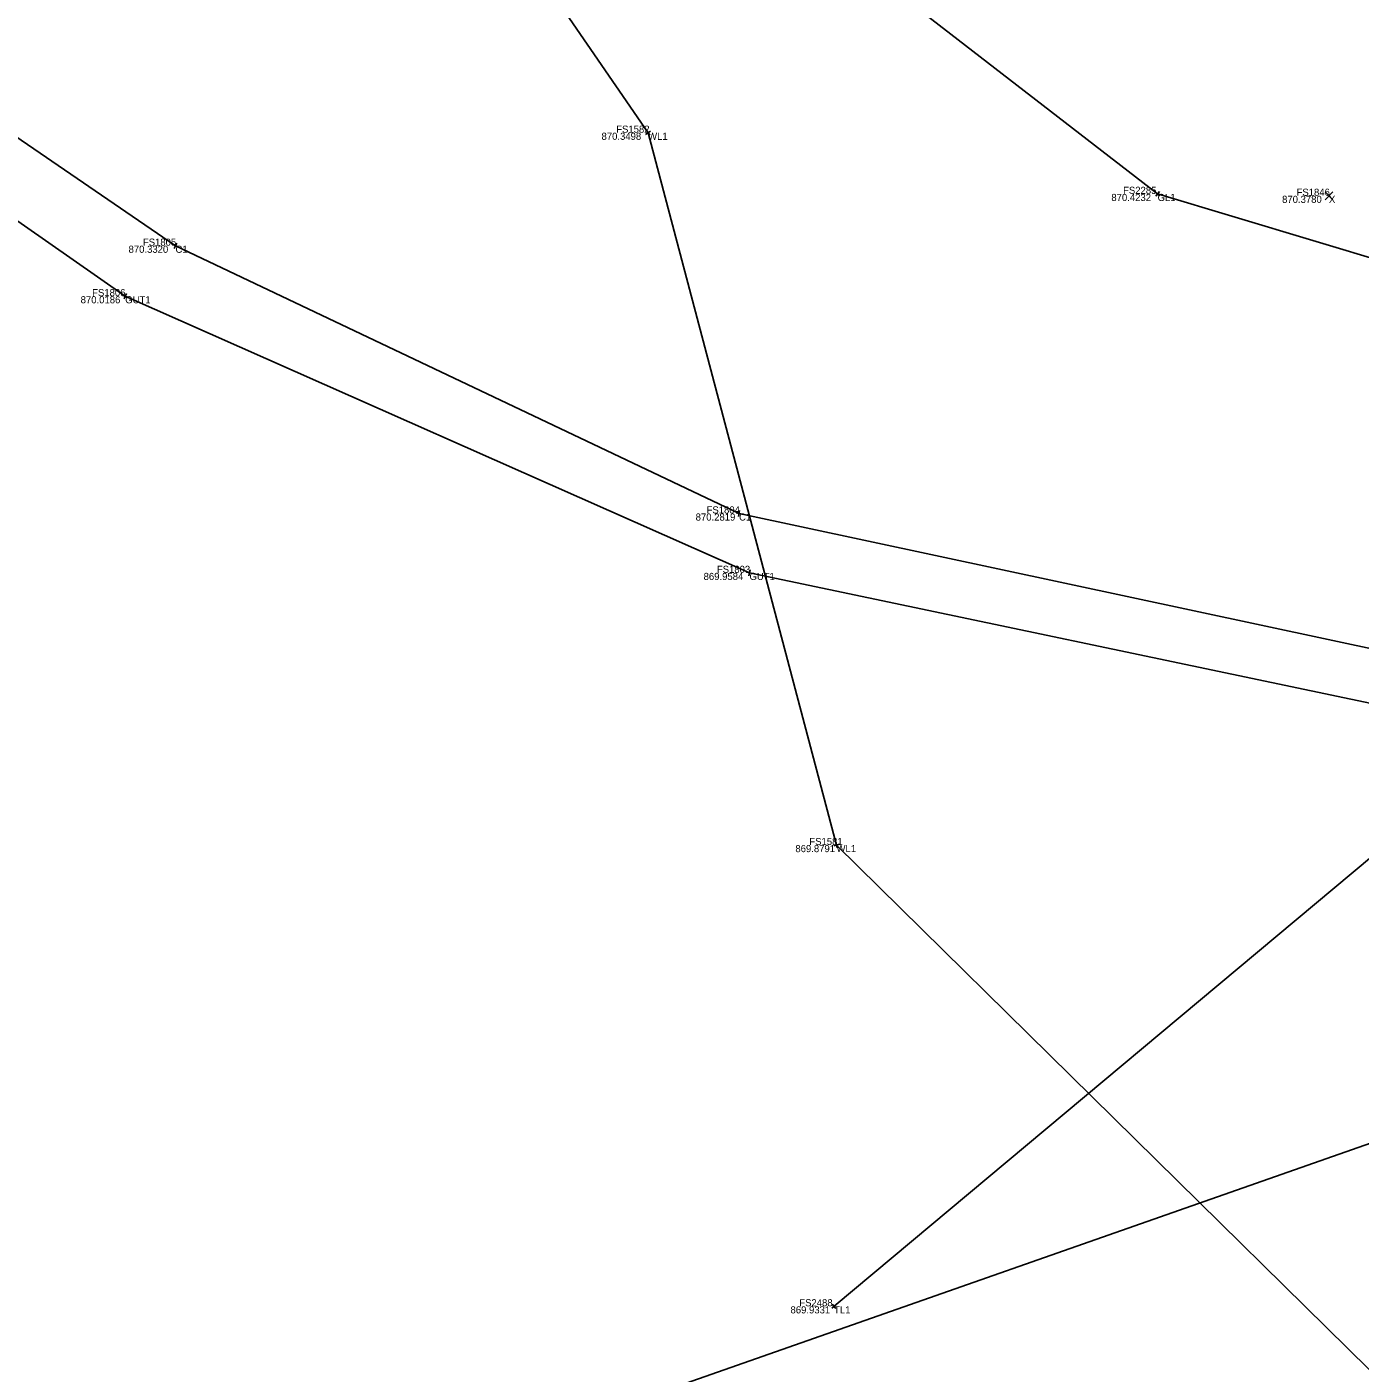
# Model space of a CAD drawing. Extents: x 1479425 to 1480294, y 379351 to 380102.
# Drawn here: x 1479647.93 to 1479659.17, y 379936.02 to 379947.37 of the extents above; entities that cross this region are included whole.
import ezdxf

# ---------------------------------------------------------------- set-up
doc = ezdxf.new("R2010")
doc.units = 0
for name, color, linetype in [('PV_X_Curb', 7, 'Continuous'), ('SV_X_Random_Point', 7, 'Continuous'), ('SV_X_Shot_Marker', 7, 'Continuous'), ('SV_X_Text_Comment', 7, 'Continuous'), ('SV_X_Text_Elevation', 7, 'Continuous'), ('SV_X_Text_Name', 7, 'Continuous'), ('UT_X_Gas', 7, 'Continuous'), ('UT_X_Sanitary_Line', 7, 'Continuous'), ('UT_X_Telecom', 7, 'Continuous'), ('UT_X_Water', 7, 'Continuous')]:
    doc.layers.add(name, color=color, linetype=linetype)

msp = doc.modelspace()

# ---------------------------------------------------------------- linework, layer by layer
at = {"layer": 'PV_X_Curb'}
for points in [[(1479791.59, 380003.464), (1479772.982, 379994.381), (1479762.438, 379989.23), (1479737.891, 379977.225), (1479720.638, 379968.611), (1479698.71, 379957.883), (1479682.413, 379949.79), (1479678.756, 379947.988), (1479678.525, 379947.942), (1479675.465, 379946.488), (1479673.909, 379945.774), (1479671.056, 379944.49), (1479670.881, 379944.45), (1479668.837, 379943.696), (1479667.016, 379943.025), (1479664.845, 379942.391), (1479664.647, 379942.335), (1479664.117, 379942.162), (1479661.876, 379941.9), (1479659.999, 379941.971), (1479653.935, 379943.268), (1479649.182, 379945.527), (1479644.261, 379948.889)], [(1479791.848, 380002.989), (1479773.254, 379993.873), (1479762.766, 379988.772), (1479738.122, 379976.643), (1479720.845, 379968.214), (1479698.694, 379957.239), (1479682.744, 379949.362), (1479678.802, 379947.48), (1479675.687, 379946.021), (1479671.323, 379944.026), (1479668.99, 379943.106), (1479665.638, 379942.041), (1479664.143, 379941.582), (1479662.026, 379941.397), (1479659.994, 379941.512), (1479654.023, 379942.767), (1479648.758, 379945.101), (1479643.81, 379948.553)]]:
    msp.add_lwpolyline(points, dxfattribs=at)
at = {"layer": 'SV_X_Random_Point'}
for p, q in [((1479658.877, 379945.915), (1479658.943, 379945.982)), ((1479658.877, 379945.982), (1479658.943, 379945.915))]:
    msp.add_line(p, q, dxfattribs=at)
at = {"layer": 'SV_X_Shot_Marker'}
for p, q in [((1479653.189, 379946.494), (1479653.147, 379946.466)), ((1479653.154, 379946.501), (1479653.182, 379946.46)), ((1479653.168, 379946.48), (1479653.168, 379946.48)), ((1479657.445, 379945.979), (1479657.485, 379945.948)), ((1479657.48, 379945.983), (1479657.45, 379945.944)), ((1479657.465, 379945.964), (1479657.465, 379945.964)), ((1479649.205, 379945.516), (1479649.159, 379945.538)), ((1479649.171, 379945.504), (1479649.193, 379945.549)), ((1479649.182, 379945.527), (1479649.182, 379945.527)), ((1479648.781, 379945.091), (1479648.735, 379945.111)), ((1479648.748, 379945.078), (1479648.768, 379945.124)), ((1479648.758, 379945.101), (1479648.758, 379945.101)), ((1479653.959, 379943.262), (1479653.911, 379943.273)), ((1479653.93, 379943.243), (1479653.94, 379943.292)), ((1479653.935, 379943.268), (1479653.935, 379943.268)), ((1479654.047, 379942.762), (1479653.999, 379942.772)), ((1479654.018, 379942.743), (1479654.028, 379942.792)), ((1479654.023, 379942.767), (1479654.023, 379942.767)), ((1479654.781, 379940.478), (1479654.733, 379940.465)), ((1479654.751, 379940.495), (1479654.763, 379940.447)), ((1479654.757, 379940.471), (1479654.757, 379940.471)), ((1479654.717, 379936.564), (1479654.755, 379936.596)), ((1479654.72, 379936.599), (1479654.752, 379936.561)), ((1479654.736, 379936.58), (1479654.736, 379936.58))]:
    msp.add_line(p, q, dxfattribs=at)
at = {"layer": 'UT_X_Gas'}
msp.add_lwpolyline([(1479646.785, 379955.438), (1479652.981, 379949.433), (1479657.465, 379945.964), (1479660.591, 379945.024), (1479670.935, 379949.08), (1479679.157, 379953.065), (1479685.442, 379955.742), (1479689.462, 379958.127), (1479696.956, 379963.013), (1479705.088, 379967.488), (1479713.465, 379971.226), (1479723.024, 379975.676), (1479732.065, 379980.116), (1479742.535, 379985.018), (1479753.798, 379990.643), (1479767.065, 379997.456), (1479775.982, 380001.733), (1479789.966, 380007.789)], dxfattribs=at)
at = {"layer": 'UT_X_Sanitary_Line'}
msp.add_lwpolyline([(1479514.622, 379866.87), (1479542.109, 379880.195), (1479565.169, 379891.725), (1479588.442, 379902.577), (1479600.276, 379909.045), (1479620.421, 379921.063), (1479621.963, 379921.485), (1479624.647, 379923.417), (1479645.234, 379932.512), (1479652.585, 379935.616), (1479664.157, 379939.675), (1479679.103, 379944.837), (1479710.112, 379956.448), (1479736.037, 379968.233), (1479798.147, 379991.168), (1479820.4, 379999.933), (1479823.042, 380000.22)], dxfattribs=at)
at = {"layer": 'UT_X_Telecom'}
msp.add_lwpolyline([(1479654.736, 379936.58), (1479659.767, 379940.788), (1479670.95, 379944.434), (1479693.183, 379956.652)], dxfattribs=at)
at = {"layer": 'UT_X_Water'}
msp.add_lwpolyline([(1479643.418, 379958.357), (1479650.478, 379950.403), (1479653.168, 379946.48), (1479654.757, 379940.471), (1479659.938, 379935.366), (1479675.346, 379920.322), (1479682.752, 379913.809), (1479688.353, 379908.314), (1479695.924, 379900.161), (1479705.441, 379891.596), (1479719.261, 379878.171), (1479726.79, 379870.913), (1479729.608, 379870.544), (1479735.551, 379869.684), (1479739.947, 379866.49), (1479744.65, 379861.847), (1479745.833, 379856.023), (1479753.929, 379847.124), (1479764.701, 379835.97), (1479779.815, 379822.167), (1479798.248, 379804.283), (1479815.468, 379787.444)], dxfattribs=at)

# ---------------------------------------------------------------- texts
at = {"layer": 'SV_X_Text_Comment'}
for s, p in [('WL1', (1479653.168, 379946.42)), ('GL1', (1479657.465, 379945.904)), ('X', (1479658.91, 379945.888)), ('C1', (1479649.182, 379945.467)), ('GUT1', (1479648.758, 379945.041)), ('C1', (1479653.935, 379943.208)), ('GUT1', (1479654.023, 379942.707)), ('WL1', (1479654.757, 379940.411)), ('TL1', (1479654.736, 379936.52))]:
    msp.add_text(s, height=0.06, dxfattribs=at).set_placement(p)
at = {"layer": 'SV_X_Text_Elevation'}
for s, p in [('870.3498', (1479652.775, 379946.42)), ('870.4232', (1479657.075, 379945.904)), ('870.3780', (1479658.515, 379945.888)), ('870.3320', (1479648.786, 379945.467)), ('870.0186', (1479648.382, 379945.041)), ('870.2819', (1479653.569, 379943.208)), ('869.9584', (1479653.636, 379942.707)), ('869.8791', (1479654.41, 379940.411)), ('869.9331', (1479654.369, 379936.52))]:
    msp.add_text(s, height=0.06, dxfattribs=at).set_placement(p)
at = {"layer": 'SV_X_Text_Name'}
for s, p in [('FS1582', (1479652.899, 379946.48)), ('FS2285', (1479657.174, 379945.964)), ('FS1846', (1479658.637, 379945.948)), ('FS1805', (1479648.907, 379945.527)), ('FS1806', (1479648.479, 379945.101)), ('FS1804', (1479653.661, 379943.268)), ('FS1803', (1479653.748, 379942.767)), ('FS1581', (1479654.528, 379940.471)), ('FS2488', (1479654.443, 379936.58))]:
    msp.add_text(s, height=0.06, dxfattribs=at).set_placement(p)

doc.saveas('drawing.dxf')
